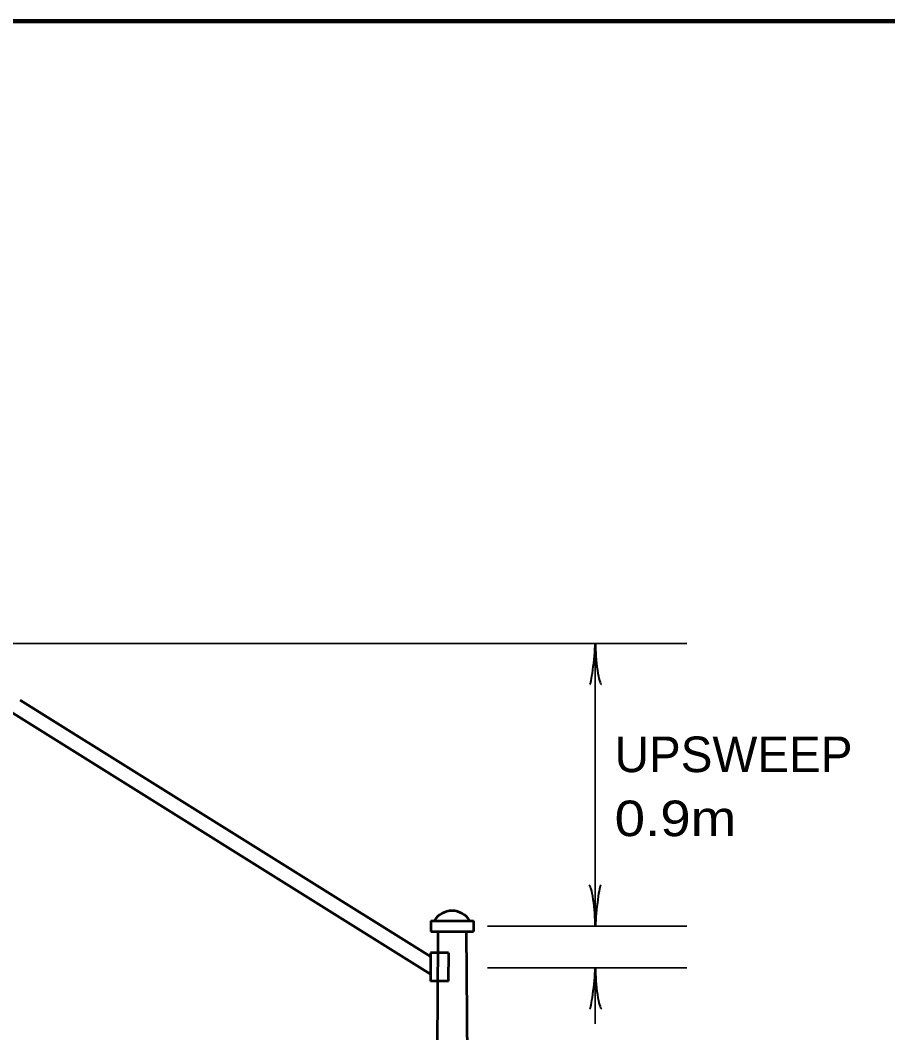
# Model space of a CAD drawing. Extents: x 6460 to 7173, y 270 to 723.
# Drawn here: x 6584 to 6645, y 646.6 to 717.8 of the extents above; entities that cross this region are included whole.
import ezdxf

# ---------------------------------------------------------------- set-up
doc = ezdxf.new("R2010")
doc.units = 0
doc.layers.add('1', color=7, linetype='Continuous', lineweight=35)

msp = doc.modelspace()

# ---------------------------------------------------------------- linework, layer by layer
at = {"layer": '1'}
for p, q in [((6573.467, 674.006), (6630.842, 674.006)), ((6624.41, 674.006), (6624.41, 654.131)), ((6630.842, 654.131), (6616.842, 654.131)), ((6630.842, 651.207), (6616.842, 651.207)), ((6624.41, 651.207), (6624.41, 647.256))]:
    msp.add_line(p, q, dxfattribs=at)
at = {"layer": '1', "lineweight": 53}
for p, q in [((6612.832, 652.006), (6583.998, 670.023)), ((6612.825, 650.756), (6583.143, 669.303)), ((6612.842, 654.506), (6615.842, 654.506)), ((6612.842, 654.506), (6612.842, 653.756)), ((6615.842, 654.506), (6615.842, 653.756)), ((6612.842, 653.756), (6615.842, 653.756)), ((6615.342, 653.756), (6616.092, 525.256)), ((6612.833, 652.256), (6612.822, 650.256)), ((6614.083, 652.256), (6612.833, 652.256)), ((6614.083, 652.256), (6614.072, 650.256)), ((6613.322, 650.256), (6612.592, 525.256)), ((6614.083, 650.256), (6612.822, 650.256))]:
    msp.add_line(p, q, dxfattribs=at)
at = {"layer": '1', "lineweight": 158}
msp.add_lwpolyline([(7167.871, 717.799), (6508.121, 717.715), (6508.204, 279.382)], dxfattribs=at)
at = {"layer": '1', "lineweight": 53}
msp.add_lwpolyline([(6613.342, 653.756), (6613.333, 652.256), (6613.322, 650.256)], dxfattribs=at)
msp.add_arc((6614.342, 653.748), 1.462, 31.24858, 148.75141, dxfattribs=at)
at = {"layer": '1', "lineweight": 40}
for centre, major_axis, ratio, start_param, end_param in [((6624.199, 672.885), (0.176, 1.756), 0.07063, 3.140715, 5.41811), ((6624.687, 672.915), (-0.156, 1.786), 0.122415, 0.896353, 3.141593), ((6624.134, 655.222), (0.156, -1.786), 0.122415, 0.896353, 3.141593), ((6624.622, 655.252), (-0.176, -1.756), 0.07063, 3.140715, 5.41811), ((6624.199, 650.087), (0.176, 1.756), 0.07063, 3.140715, 5.41811), ((6624.687, 650.116), (-0.156, 1.786), 0.122415, 0.896353, 3.141593)]:
    msp.add_ellipse(centre, major_axis=major_axis, ratio=ratio, start_param=start_param, end_param=end_param, dxfattribs=at)

# ---------------------------------------------------------------- texts
at = {"layer": '1'}
msp.add_text('UPSWEEP', height=2.5, dxfattribs=at).set_placement((6625.767, 664.957))
at = {"layer": '1', "width": 1.15}
msp.add_text('0.9m', height=2.5, dxfattribs=at).set_placement((6625.767, 660.457))

doc.saveas('drawing.dxf')
